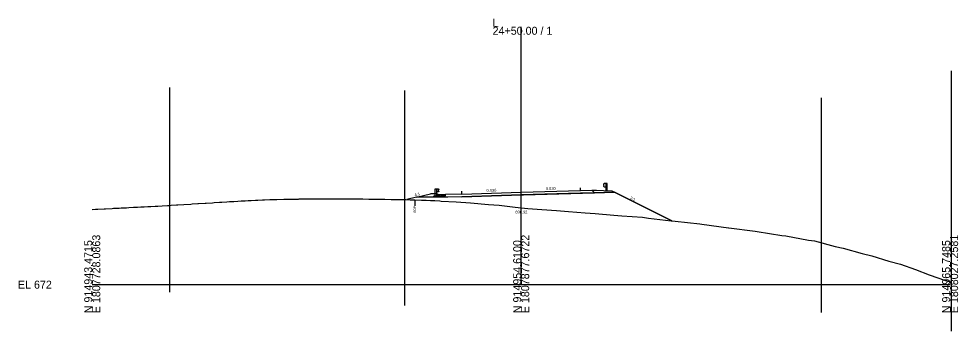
# Model space of a CAD drawing. Extents: x -26 to 1352, y -510 to 9596.
# Drawn here: x 974.3 to 1302.8, y 483.7 to 593.1 of the extents above; entities that cross this region are included whole.
import ezdxf

# ---------------------------------------------------------------- set-up
doc = ezdxf.new("R2010")
doc.units = 0
for name, color, linetype in [('Exist Cross Section Cell', 7, 'Continuous'), ('Exist XS Center Line Elevation Label', 7, 'Continuous'), ('Exist XS Ground Line', 7, 'Continuous'), ('Old_Level_10', 7, 'Continuous'), ('Prop XS Ditch Slope Text', 7, 'Continuous'), ('Prop XS Earthwork Shape', 7, 'Continuous'), ('Prop XS EOT Tick Mark', 7, 'Continuous'), ('Prop XS Exc Vertical Line 1', 7, 'Continuous'), ('Prop XS Exc Vertical Line 2', 7, 'Continuous'), ('Prop XS Exc Vertical Line 3', 7, 'Continuous'), ('Prop XS Exc Vertical Line 4', 7, 'Continuous'), ('Prop XS Finish Grade', 7, 'Continuous'), ('Prop XS Finish Grade Earthwork', 7, 'Continuous'), ('Prop XS Finish Grade Paved Shoulder', 7, 'Continuous'), ('Prop XS Finish Grade Pavement', 7, 'Continuous'), ('Prop XS Guardrail', 7, 'Continuous'), ('Prop XS Hydro Fill Slope Data', 7, 'Continuous'), ('Prop XS Pvmt Edge Slope', 7, 'Continuous'), ('Prop XS SE Text', 7, 'Continuous'), ('Prop XS Side Slope Text', 7, 'Continuous'), ('Prop XS Subgrade Earthwork', 7, 'Continuous'), ('Typical Curb CELL', 7, 'Continuous')]:
    doc.layers.add(name, color=color, linetype=linetype)

msp = doc.modelspace()

# ---------------------------------------------------------------- linework, layer by layer
at = {"layer": 'Exist Cross Section Cell'}
for p, q in [((1150, 500), (1150, 590.33)), ((1000, 500), (1150, 500)), ((1150, 500), (1300, 500))]:
    msp.add_line(p, q, dxfattribs=at)
at = {"layer": 'Exist XS Ground Line'}
msp.add_lwpolyline([(1000, 526.38), (1001.19, 526.44), (1001.87, 526.47), (1001.92, 526.48), (1004.21, 526.58), (1004.43, 526.59), (1004.68, 526.6), (1006.94, 526.71), (1007.4, 526.74), (1009.45, 526.84), (1010.1, 526.87), (1011.95, 526.96), (1012.81, 527.01), (1014.46, 527.1), (1015.88, 527.18), (1016.97, 527.23), (1018.21, 527.29), (1019.46, 527.36), (1020.53, 527.42), (1021.97, 527.5), (1022.88, 527.55), (1024.48, 527.64), (1026.36, 527.74), (1027, 527.77), (1027.55, 527.81), (1029.5, 527.92), (1029.87, 527.94), (1032, 528.08), (1034.48, 528.23), (1034.51, 528.23), (1034.52, 528.23), (1034.91, 528.26), (1036.88, 528.37), (1037.02, 528.38), (1037.19, 528.39), (1039.53, 528.55), (1039.89, 528.57), (1042.03, 528.71), (1042.6, 528.74), (1044.54, 528.87), (1045.32, 528.91), (1047.05, 529.02), (1048.03, 529.07), (1049.55, 529.17), (1050.87, 529.24), (1052.06, 529.31), (1053.44, 529.38), (1054.57, 529.45), (1055.54, 529.5), (1057.07, 529.56), (1057.87, 529.61), (1059.58, 529.69), (1060.21, 529.71), (1062.08, 529.78), (1062.54, 529.8), (1064.6, 529.85), (1066.98, 529.9), (1067.1, 529.9), (1068.6, 529.94), (1069.53, 529.97), (1069.6, 529.97), (1071.87, 530), (1072.12, 530), (1072.41, 530.01), (1074.63, 530.03), (1076.54, 530.04), (1077.14, 530.05), (1077.83, 530.06), (1079.64, 530.07), (1080.53, 530.07), (1082.15, 530.08), (1083.24, 530.09), (1084.66, 530.11), (1085.96, 530.11), (1087.16, 530.11), (1088.2, 530.1), (1089.67, 530.08), (1091.36, 530.06), (1092.17, 530.05), (1094.07, 530.03), (1094.68, 530.03), (1096.78, 530), (1097.19, 530), (1097.34, 529.99), (1097.92, 529.99), (1099.5, 529.96), (1099.69, 529.95), (1099.87, 529.95), (1102.2, 529.91), (1102.32, 529.91), (1104.54, 529.87), (1104.71, 529.87), (1104.9, 529.86), (1107.22, 529.82), (1107.75, 529.82), (1109.5, 529.8), (1109.64, 529.8), (1111.18, 529.75), (1112.22, 529.72), (1112.53, 529.7), (1112.8, 529.69), (1115.09, 529.62), (1116.83, 529.56), (1118.26, 529.5), (1118.78, 529.49), (1119.37, 529.47), (1119.77, 529.45), (1121.52, 529.37), (1122.05, 529.25), (1127.23, 528.97), (1132.28, 528.63), (1138.54, 528.1), (1142.31, 527.81), (1147.87, 527.12), (1150, 526.92), (1152.33, 526.71), (1157.2, 526.38), (1162.36, 525.97), (1166.54, 525.63), (1172.39, 525.18), (1175.87, 524.98), (1182.42, 524.33), (1185.2, 524.16), (1192.45, 523.59), (1194.53, 523.24), (1202.47, 522.41), (1203.87, 522.24), (1212.5, 521.26), (1213.2, 521.16), (1222.53, 519.95), (1222.53, 519.95), (1222.59, 519.95), (1231.86, 518.69), (1232.56, 518.62), (1241.2, 517.27), (1242.58, 517.07), (1250.53, 515.58), (1252.61, 515.31), (1259.86, 513.37), (1262.64, 512.79), (1269.2, 510.96), (1272.67, 510.13), (1278.53, 508.25), (1282.69, 507.22), (1287.86, 505.29), (1292.72, 503.49), (1298.36, 501.42), (1300, 500.95)], dxfattribs=at)
at = {"layer": 'Old_Level_10'}
msp.add_line((1112.8, 529.69), (1112.8, 527.64), dxfattribs=at)
at = {"layer": 'Prop XS Earthwork Shape'}
msp.add_lwpolyline([(1175.87, 524.98), (1182.42, 524.33), (1185.2, 524.16), (1192.45, 523.59), (1194.53, 523.24), (1202.47, 522.41), (1202.74, 522.38), (1182.69, 532.4), (1175.64, 532.19), (1170.75, 532.04), (1150, 531.42), (1146.67, 531.32), (1129.25, 530.8), (1124.3, 530.65), (1123.58, 530.63), (1113.35, 530.63), (1109.96, 529.78), (1112.85, 529.69), (1115.09, 529.62), (1116.83, 529.56), (1118.26, 529.5), (1118.78, 529.49), (1119.37, 529.47), (1119.77, 529.45), (1121.52, 529.37), (1122.05, 529.25), (1127.23, 528.97), (1132.28, 528.63), (1138.54, 528.1), (1142.31, 527.81), (1147.87, 527.12), (1150, 526.92), (1152.33, 526.71), (1157.2, 526.38), (1162.36, 525.97), (1166.54, 525.63), (1172.39, 525.18)], close=True, dxfattribs=at)
at = {"layer": 'Prop XS EOT Tick Mark'}
for p, q in [((1129.25, 531.72), (1129.25, 532.72)), ((1170.75, 532.96), (1170.75, 533.96))]:
    msp.add_line(p, q, dxfattribs=at)
at = {"layer": 'Prop XS Exc Vertical Line 1'}
msp.add_line((1027.1, 497.37), (1027.1, 569.02), dxfattribs=at)
at = {"layer": 'Prop XS Exc Vertical Line 2'}
msp.add_line((1109.26, 492.72), (1109.26, 567.95), dxfattribs=at)
at = {"layer": 'Prop XS Exc Vertical Line 3'}
msp.add_line((1255.02, 490.2), (1255.02, 565.44), dxfattribs=at)
at = {"layer": 'Prop XS Exc Vertical Line 4'}
msp.add_line((1300.5, 483.69), (1300.5, 574.88), dxfattribs=at)
at = {"layer": 'Prop XS Finish Grade'}
for p, q in [((1174.75, 533.08), (1176.32, 533.04)), ((1176.32, 533.04), (1178.75, 532.96)), ((1178.75, 532.96), (1181.75, 532.87)), ((1181.75, 532.87), (1182.69, 532.4)), ((1182.69, 532.4), (1182.69, 532.4)), ((1113.35, 530.63), (1118.25, 531.85)), ((1120.56, 531.81), (1118.25, 531.85))]:
    msp.add_line(p, q, dxfattribs=at)
at = {"layer": 'Prop XS Finish Grade Earthwork'}
for p, q in [((1182.69, 532.4), (1202.74, 522.38)), ((1113.35, 530.63), (1109.96, 529.78))]:
    msp.add_line(p, q, dxfattribs=at)
at = {"layer": 'Prop XS Finish Grade Paved Shoulder'}
for p, q in [((1170.75, 532.96), (1174.75, 533.08)), ((1129.25, 531.72), (1123.58, 531.55))]:
    msp.add_line(p, q, dxfattribs=at)
at = {"layer": 'Prop XS Finish Grade Pavement'}
for p, q in [((1129.25, 531.72), (1150, 532.34)), ((1150, 532.34), (1170.75, 532.96))]:
    msp.add_line(p, q, dxfattribs=at)
at = {"layer": 'Prop XS Guardrail'}
for p, q in [((1119.93, 533.62), (1120.43, 533.62)), ((1119.93, 531.12), (1119.93, 533.62)), ((1120.43, 533.62), (1120.93, 533.62)), ((1120.43, 533.62), (1120.43, 531.12)), ((1120.93, 532.48), (1120.43, 532.48)), ((1120.93, 533.62), (1121.22, 533.42)), ((1121.22, 533.3), (1120.93, 533.1)), ((1120.93, 533.1), (1120.93, 533)), ((1120.93, 533), (1121.22, 532.8)), ((1121.22, 532.68), (1120.93, 532.48)), ((1121.22, 533.42), (1121.25, 533.36)), ((1121.25, 533.36), (1121.22, 533.3)), ((1121.22, 532.8), (1121.25, 532.74)), ((1121.25, 532.74), (1121.22, 532.68)), ((1178.78, 535.22), (1178.75, 535.16)), ((1178.75, 535.16), (1178.78, 535.1)), ((1178.78, 534.61), (1178.75, 534.55)), ((1178.75, 534.55), (1178.78, 534.49)), ((1179.07, 535.42), (1178.78, 535.22)), ((1178.78, 535.1), (1179.07, 534.9)), ((1179.07, 534.81), (1178.78, 534.61)), ((1178.78, 534.49), (1179.07, 534.29)), ((1179.57, 535.42), (1179.07, 535.42)), ((1179.07, 534.9), (1179.07, 534.81)), ((1179.07, 534.29), (1179.57, 534.29)), ((1180.07, 535.42), (1179.57, 535.42)), ((1179.57, 535.42), (1179.57, 532.92)), ((1180.07, 532.92), (1180.07, 535.42))]:
    msp.add_line(p, q, dxfattribs=at)
at = {"layer": 'Prop XS Hydro Fill Slope Data'}
msp.add_line((1181.75, 532.87), (1202.74, 522.38), dxfattribs=at)
at = {"layer": 'Prop XS Pvmt Edge Slope'}
for p, q in [((1174.75, 533.08), (1175.64, 532.19)), ((1119.56, 531.13), (1119.06, 530.63)), ((1119.56, 531.13), (1120.56, 531.13))]:
    msp.add_line(p, q, dxfattribs=at)
at = {"layer": 'Prop XS Subgrade Earthwork'}
for p, q in [((1175.64, 532.19), (1182.69, 532.4)), ((1119.05, 530.63), (1113.35, 530.63)), ((1123.58, 530.63), (1119.05, 530.63)), ((1129.25, 530.8), (1123.58, 530.63)), ((1129.25, 530.8), (1150, 531.42)), ((1146.67, 531.32), (1175.64, 532.19)), ((1150, 531.42), (1170.75, 532.04))]:
    msp.add_line(p, q, dxfattribs=at)
at = {"layer": 'Typical Curb CELL'}
for p, q in [((1120.56, 531.13), (1120.56, 531.81)), ((1121.25, 531.46), (1120.56, 531.81)), ((1120.56, 531.13), (1123.58, 531.13)), ((1120.6, 531.43), (1120.75, 531.47)), ((1120.74, 531.38), (1120.6, 531.43)), ((1120.75, 531.47), (1120.74, 531.38)), ((1121.27, 531.35), (1121.17, 531.27)), ((1121.17, 531.27), (1121.33, 531.23)), ((1123.57, 531.55), (1121.25, 531.46)), ((1121.33, 531.23), (1121.27, 531.35)), ((1122.01, 531.4), (1121.98, 531.29)), ((1121.98, 531.29), (1122.1, 531.28)), ((1122.1, 531.28), (1122.01, 531.4)), ((1122.52, 531.35), (1122.41, 531.27)), ((1122.41, 531.27), (1122.58, 531.23)), ((1122.58, 531.23), (1122.52, 531.35)), ((1123.26, 531.4), (1123.22, 531.29)), ((1123.22, 531.29), (1123.35, 531.28)), ((1123.35, 531.28), (1123.26, 531.4)), ((1123.58, 531.55), (1123.58, 531.55)), ((1123.58, 531.13), (1123.58, 531.54))]:
    msp.add_line(p, q, dxfattribs=at)
for centre in [(1120.63, 531.52), (1120.72, 531.24), (1120.84, 531.29), (1121.1, 531.32), (1121.12, 531.27), (1121.3, 531.18), (1121.32, 531.29), (1121.52, 531.25), (1121.56, 531.36), (1121.69, 531.33), (1121.72, 531.21), (1121.78, 531.24), (1121.97, 531.24), (1122.09, 531.29), (1122.19, 531.28), (1122.28, 531.24), (1122.34, 531.38), (1122.35, 531.32), (1122.37, 531.27), (1122.57, 531.29), (1122.77, 531.25), (1122.81, 531.36), (1122.86, 531.33), (1122.94, 531.33), (1122.97, 531.21), (1123.03, 531.24), (1123.09, 531.42), (1123.46, 531.49), (1123.49, 531.37)]:
    msp.add_circle(centre, 0.00802, dxfattribs=at)
msp.add_arc((1123.57, 531.54), 0.0104, 0, 92.048, dxfattribs=at)

# ---------------------------------------------------------------- texts
at = {"layer": 'Exist Cross Section Cell'}
for s, p in [('L', (1140, 590.33)), ('24+50.00 / 1', (1140, 587.53)), ('EL 672', (974, 498.6))]:
    msp.add_text(s, height=2.8, dxfattribs=at).set_placement(p)
for s, p in [('E 1807728.0863', (1002.8, 490)), ('E 1807877.6722', (1152.8, 490)), ('E 1808027.2581', (1302.8, 490)), ('N 914943.4715', (1000, 490)), ('N 914954.6100', (1150, 490)), ('N 914965.7485', (1300, 490))]:
    msp.add_text(s, height=2.8, rotation=90, dxfattribs=at).set_placement(p)
at = {"layer": 'Exist XS Center Line Elevation Label'}
msp.add_text('698.92', height=1, dxfattribs=at).set_placement((1147.96, 524.92))
at = {"layer": 'Old_Level_10'}
msp.add_text('EOP', height=0.787, rotation=90, dxfattribs=at).set_placement((1113.19, 525.24))
at = {"layer": 'Prop XS Ditch Slope Text'}
msp.add_text('4:1', height=1, rotation=14.0362, dxfattribs=at).set_placement((1112.85, 530.93))
at = {"layer": 'Prop XS SE Text'}
for p in [(1137.88, 532.48), (1158.63, 533.1)]:
    msp.add_text('0.030', height=1, rotation=1.7184, dxfattribs=at).set_placement(p)
at = {"layer": 'Prop XS Side Slope Text'}
msp.add_text('2:1', height=1, rotation=333.4349, dxfattribs=at).set_placement((1187.98, 530.04))

doc.saveas('drawing.dxf')
